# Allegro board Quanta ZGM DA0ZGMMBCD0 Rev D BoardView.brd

Outline 323.4 x 222.55 mm; copper layers: TOP, SGND, IN1, SGND1, IN2, SVCC, SVCC1, IN3, SGND2, IN4, SGND3, BOTTOM. Coordinates in mm from the lower left corner of the outline.
Outline path: 0,100.22 0,98.15 0.5,97.64 5.68,97.64 arc(6.18,98.15) 6.68,97.64 6.68,88.3 arc(6.18,87.81) 5.68,88.3 1,88.3 1,83.64 5.68,83.64 arc(6.18,84.15) 6.68,83.64 6.68,74.3 arc(6.18,73.81) 5.68,74.3 0.5,74.3 0,73.8 0,72.35 0.5,71.85 1.6,71.85 2,71.45 2,70.4 2.4,70 4,70 arc(5.25,68.75) 4,67.5 2.4,67.5 2,67.1 2,63.76 2.1,63.76 2.5,63.36 2.5,62.05 2.1,61.65 0.5,61.65 0,61.15 0,59.4 13.8,59.4 arc(14.3,58.9) 13.8,58.4 13.8,46.7 arc(14.3,46.2) 13.8,45.7 0,45.7 0,43.8 2.2,43.8 2.2,40.8 8.69,40.8 arc(9.19,41.3) 9.69,40.8 9.69,25.2 arc(9.19,24.7) 8.69,25.2 0,25.2 0,22.71 1.6,22.71 2,22.31 2,19.71 11.5,19.71 arc(11.9,19.31) 11.5,18.91 11.5,11.41 arc(11.9,11.01) 11.5,10.61 2,10.61 2,1.5 3.5,0 28.41,0 arc(29.12,0.29) 29.41,1 29.41,29 32.41,32 51.41,32 51.41,36 58.2,36 60.7,38.5 118.7,38.5 120.7,36.5 215.7,36.5 218.2,34 220.9,34 221.4,34.5 221.4,37 arc(222.7,38.3) 224,37 224,34.5 224.5,34 273.19,34 273.69,34.5 273.69,37 arc(274.99,38.3) 276.29,37 276.29,34.5 276.79,34 289.6,34 arc(290.31,34.29) 290.6,35 290.6,54.2 293.6,57.2 322.4,57.2 arc(323.11,57.49) 323.4,58.2 323.4,101.52 arc(323.19,102.13) 322.65,102.48 arc(318.22,103.89) 313.96,105.74 arc(313.62,105.78) 313.33,105.58 312.43,104.28 arc(305.61,103.03) 304.37,109.85 305.12,110.94 arc(305.2,111.29) 305.02,111.61 arc(304.61,111.95) 304.21,112.3 arc(293.01,127.38) 288.9,145.71 288.9,218.9 arc(288.61,219.61) 287.9,219.9 252.9,219.9 252.9,220.65 arc(252.61,221.36) 251.9,221.65 221.74,221.65 arc(220.15,222.55) 218.56,221.65 218.45,221.65 218.45,210.78 arc(218.8,209.93) 217.95,210.28 205.85,210.28 arc(205,209.93) 205.35,210.78 205.35,221.65 205.24,221.65 arc(203.65,222.55) 202.06,221.65 193.74,221.65 arc(192.15,222.55) 190.56,221.65 190.45,221.65 190.45,210.78 arc(190.8,209.93) 189.95,210.28 177.85,210.28 arc(177,209.93) 177.35,210.78 177.35,221.65 177.24,221.65 arc(175.65,222.55) 174.06,221.65 143.9,221.65 arc(143.19,221.36) 142.9,220.65 142.9,219.9 107.9,219.9 arc(107.19,219.61) 106.9,218.9 106.9,147.91 arc(102.73,128.68) 90.96,112.92 arc(90.62,112.62) 90.27,112.34 arc(90.1,112.02) 90.18,111.67 91.43,109.85 arc(90.19,103.03) 83.37,104.28 81.66,106.75 arc(81.38,106.95) 81.04,106.93 arc(72.31,104.15) 63.2,103.21 4.3,103.21 arc(3.59,102.92) 3.3,102.21 3.3,100.22 0,100.22

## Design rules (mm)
constraint set DEFAULT: min track width 0.14
net group DFP-S5W5-T14B: nets VGPU_CORE_SENSE VSS_GPU_SENSE
net group DFP-S7W5.5-TB: nets VGA_XTALIN VGA_XTALOUT
net group W5.5-T1234B: nets SUSCLK SUSCLK_32K
net group W25-T1234B: nets LED_PWR_LEFT LED_PWR_RIGHT
net group DFP-S3.5(4.5)W6(5)-T14B: nets M_A_CLKN0 M_A_CLKN1 M_A_CLKP0 M_A_CLKP1 M_A_DQSN0 M_A_DQSN1 M_A_DQSN2 M_A_DQSN3 M_A_DQSN4 M_A_DQSN5 M_A_DQSN6 M_A_DQSN7 M_A_DQSP0 M_A_DQSP1 M_A_DQSP2 M_A_DQSP3 M_A_DQSP4 M_A_DQSP5 M_A_DQSP6 M_A_DQSP7 M_B_CLKN0 M_B_CLKN1 M_B_CLKP0 M_B_CLKP1 M_B_DQSN0 M_B_DQSN1 M_B_DQSN2 M_B_DQSN3 M_B_DQSN4 M_B_DQSN5 M_B_DQSN6 M_B_DQSN7 M_B_DQSP0 M_B_DQSP1 M_B_DQSP2 M_B_DQSP3 M_B_DQSP4 M_B_DQSP5 M_B_DQSP6 M_B_DQSP7
net group DFP-S4(4.5)W5.5(4.5)-T14B: nets USB3_PCH_RX_WWAN_TX_C_N USB3_PCH_RX_WWAN_TX_C_P USB3_PCH_TX_WWAN_RX_C_N USB3_PCH_TX_WWAN_RX_C_P USB30_RX+_DB1 USB30_RX+_DB2 USB30_RX+_MB1 USB30_RX+_MB1_RTO USB30_RX+_WWAN USB30_RX-_DB1 USB30_RX-_DB2 USB30_RX-_MB1 USB30_RX-_MB1_RTO USB30_RX-_WWAN USB30_TX+_DB1 USB30_TX+_DB2 USB30_TX+_MB1 USB30_TX+_MB1_RTI USB30_TX+_WWAN USB30_TX-_DB1 USB30_TX-_DB2 USB30_TX-_MB1 USB30_TX-_MB1_RTI USB30_TX-_WWAN
net group DFP-S4(4.5: nets VMA_CLK0 VMA_CLK0# VMA_CLK1 VMA_CLK1# VMA_WCK01 VMA_WCK01# VMA_WCK23 VMA_WCK23# VMA_WCK45 VMA_WCK45# VMA_WCK67 VMA_WCK67# VMA_WCKB01 VMA_WCKB01# VMA_WCKB23 VMA_WCKB23# VMA_WCKB45 VMA_WCKB45# VMA_WCKB67 VMA_WCKB67# VMB_CLK0 VMB_CLK0# VMB_CLK1 VMB_CLK1# VMB_WCK01 VMB_WCK01# VMB_WCK23 VMB_WCK23# VMB_WCK45 VMB_WCK45# VMB_WCK67 VMB_WCK67# VMB_WCKB01 VMB_WCKB01# VMB_WCKB23 VMB_WCKB23# VMB_WCKB45 VMB_WCKB45# VMB_WCKB67 VMB_WCKB67# VMC_CLK0 VMC_CLK0# VMC_CLK1 VMC_CLK1# VMC_WCK01 VMC_WCK01# VMC_WCK23 VMC_WCK23# VMC_WCK45 VMC_WCK45# VMC_WCK67 VMC_WCK67# VMC_WCKB01 VMC_WCKB01# VMC_WCKB23 VMC_WCKB23# VMC_WCKB45 VMC_WCKB45# VMC_WCKB67 VMC_WCKB67# VMD_CLK0 VMD_CLK0# VMD_CLK1 VMD_CLK1# VMD_WCK01 VMD_WCK01# VMD_WCK23 VMD_WCK23# VMD_WCK45 VMD_WCK45# VMD_WCK67 VMD_WCK67# VMD_WCKB01 VMD_WCKB01# VMD_WCKB23 VMD_WCKB23# VMD_WCKB45 VMD_WCKB45# VMD_WCKB67 VMD_WCKB67#
net group DFP-S5(3.1)W5.5(3.4)-T4B: nets GPU_EDP_AUXN GPU_EDP_AUXN_R GPU_EDP_AUXP GPU_EDP_AUXP_R GPU_EDP_TXN0 GPU_EDP_TXN0_R GPU_EDP_TXN1 GPU_EDP_TXN1_R GPU_EDP_TXN2 GPU_EDP_TXN2_R GPU_EDP_TXN3 GPU_EDP_TXN3_R GPU_EDP_TXP0 GPU_EDP_TXP0_R GPU_EDP_TXP1 GPU_EDP_TXP1_R GPU_EDP_TXP2 GPU_EDP_TXP2_R GPU_EDP_TXP3 GPU_EDP_TXP3_R INT_EDP_AUXN INT_EDP_AUXN_R INT_EDP_AUXP INT_EDP_AUXP_R INT_EDP_TXN0 INT_EDP_TXN0_R INT_EDP_TXN1 INT_EDP_TXN1_R INT_EDP_TXN2 INT_EDP_TXN2_R INT_EDP_TXN3 INT_EDP_TXN3_R INT_EDP_TXP0 INT_EDP_TXP0_R INT_EDP_TXP1 INT_EDP_TXP1_R INT_EDP_TXP2 INT_EDP_TXP2_R INT_EDP_TXP3 INT_EDP_TXP3_R
net group DFP-S5(3.1)W5.5(3.4)-T14B: nets 8816ARGDN 8816AVSNS FVDDQ_SENSE_I FVDDQ_SENSE_V INA199_IN+ INA199_IN- NVVDD_SENSE_I NVVDD_SENSE_V TCP0_AUX_DN TCP0_AUX_DN_R TCP0_AUX_DP TCP0_AUX_DP_R TCP0_TX_N0 TCP0_TX_N0_C TCP0_TX_N1 TCP0_TX_N1_C TCP0_TX_P0 TCP0_TX_P0_C TCP0_TX_P1 TCP0_TX_P1_C TCP0_TXRX_N0 TCP0_TXRX_N0_C TCP0_TXRX_N1 TCP0_TXRX_N1_C TCP0_TXRX_P0 TCP0_TXRX_P0_C TCP0_TXRX_P1 TCP0_TXRX_P1_C TCP2_AUX_DN TCP2_AUX_DN_R TCP2_AUX_DP TCP2_AUX_DP_R TCP2_TX_N0 TCP2_TX_N0_C TCP2_TX_N1 TCP2_TX_N1_C TCP2_TX_P0 TCP2_TX_P0_C TCP2_TX_P1 TCP2_TX_P1_C TCP2_TXRX_N0 TCP2_TXRX_N0_C TCP2_TXRX_N1 TCP2_TXRX_N1_C TCP2_TXRX_P0 TCP2_TXRX_P0_C TCP2_TXRX_P1 TCP2_TXRX_P1_C
net group DFP-S5(3.1: nets TBT_SBU1_P1_CON_S TBT_SBU1_P2_CON_S TBT_SBU2_P1_CON_S TBT_SBU2_P2_CON_S
net group DFP-S5(3.1: nets CNV_WR_CLK_DN CNV_WR_CLK_DP CNV_WR_LANE0_DN CNV_WR_LANE0_DP CNV_WR_LANE1_DN CNV_WR_LANE1_DP CNV_WT_CLK_DN CNV_WT_CLK_DP CNV_WT_LANE0_DN CNV_WT_LANE0_DP CNV_WT_LANE1_DN CNV_WT_LANE1_DP
net group DFP-S5(3.1: nets 24780_ACN 24780_ACP 24780_SRN 24780_SRP CLK_CPU_BCLKN CLK_CPU_BCLKP CLK_DPLL_NSCCLKN CLK_DPLL_NSCCLKN_C CLK_DPLL_NSCCLKP CLK_DPLL_NSCCLKP_C CLK_PCIE_LANN CLK_PCIE_LANP CLK_PCIE_SSD1N CLK_PCIE_SSD1N_R CLK_PCIE_SSD1P CLK_PCIE_SSD1P_R CLK_PCIE_SSDN CLK_PCIE_SSDN_R CLK_PCIE_SSDP CLK_PCIE_SSDP_R CLK_PCIE_WLANN CLK_PCIE_WLANP CLK_PCIE_WWANN CLK_PCIE_WWANP CLK_VGA_N CLK_VGA_P CPU_PCI_BCLKN CPU_PCI_BCLKP GPU_ADC_INN GPU_ADC_INP GPU_THERMDA GPU_THERMDC MBCLK1_GPU MBDATA1_GPU PCIE_8_PCH_RX_WWAN_TX_C_N PCIE_8_PCH_RX_WWAN_TX_C_P PCIE_8_PCH_TX_WWAN_RX_C_N PCIE_8_PCH_TX_WWAN_RX_C_P PCIE_RXN8_WWAN PCIE_RXN_LAN PCIE_RXN_WLAN PCIE_RXP8_WWAN PCIE_RXP_LAN PCIE_RXP_WLAN PCIE_TXN8_WWAN PCIE_TXN_LAN PCIE_TXN_WLAN PCIE_TXN_WLAN_C PCIE_TXP8_WWAN PCIE_TXP_LAN PCIE_TXP_WLAN PCIE_TXP_WLAN_C PEG11_RXN0_SSD PEG11_RXN0_SSD_R PEG11_RXN1_SSD PEG11_RXN1_SSD_R PEG11_RXN2_SSD PEG11_RXN2_SSD_R PEG11_RXN3_SSD PEG11_RXN3_SSD_R PEG11_RXP0_SSD PEG11_RXP0_SSD_R PEG11_RXP1_SSD PEG11_RXP1_SSD_R PEG11_RXP2_SSD PEG11_RXP2_SSD_R PEG11_RXP3_SSD PEG11_RXP3_SSD_R PEG11_TXN0_SSD PEG11_TXN0_SSD_R PEG11_TXN1_SSD PEG11_TXN1_SSD_R PEG11_TXN2_SSD PEG11_TXN2_SSD_R PEG11_TXN3_SSD PEG11_TXN3_SSD_R PEG11_TXP0_SSD PEG11_TXP0_SSD_R PEG11_TXP1_SSD PEG11_TXP1_SSD_R PEG11_TXP2_SSD PEG11_TXP2_SSD_R PEG11_TXP3_SSD PEG11_TXP3_SSD_R PEG12_RXN0_SSD PEG12_RXN0_SSD_R PEG12_RXN1_SSD PEG12_RXN1_SSD_R PEG12_RXN2_SSD PEG12_RXN2_SSD_R PEG12_RXN3_SSD PEG12_RXN3_SSD_R PEG12_RXP0_SSD PEG12_RXP0_SSD_R PEG12_RXP1_SSD PEG12_RXP1_SSD_R PEG12_RXP2_SSD PEG12_RXP2_SSD_R PEG12_RXP3_SSD PEG12_RXP3_SSD_R PEG12_TXN0_SSD PEG12_TXN0_SSD_R PEG12_TXN1_SSD PEG12_TXN1_SSD_R PEG12_TXN2_SSD PEG12_TXN2_SSD_R PEG12_TXN3_SSD PEG12_TXN3_SSD_R PEG12_TXP0_SSD PEG12_TXP0_SSD_R PEG12_TXP1_SSD PEG12_TXP1_SSD_R PEG12_TXP2_SSD PEG12_TXP2_SSD_R PEG12_TXP3_SSD PEG12_TXP3_SSD_R SATA_RXN0_CN SATA_RXN0_HDD SATA_RXN_IN SATA_RXN_OUT SATA_RXP0_CN SATA_RXP0_HDD SATA_RXP_IN SATA_RXP_OUT SATA_TXN0_CN SATA_TXN0_HDD SATA_TXN_IN SATA_TXN_OUT SATA_TXP0_CN SATA_TXP0_HDD SATA_TXP_IN SATA_TXP_OUT TBT_LSX0_RXD TBT_LSX0_RXD_C TBT_LSX0_TXD TBT_LSX0_TXD_C TBT_LSX2_RXD TBT_LSX2_RXD_C TBT_LSX2_TXD TBT_LSX2_TXD_C USBP+_CCD USBP+_CCD_R USBP+_DB1 USBP+_DB1_C USBP+_DB2 USBP+_DB2_C USBP+_KB USBP+_MB USBP+_MB_C USBP+_MB_C_R USBP+_TC1 USBP+_TC2 USBP+_WLAN USBP+_WWAN USBP+_WWAN_R USBP-_CCD USBP-_CCD_R USBP-_DB1 USBP-_DB1_C USBP-_DB2 USBP-_DB2_C USBP-_KB USBP-_MB USBP-_MB_C USBP-_MB_C_R USBP-_TC1 USBP-_TC2 USBP-_WLAN USBP-_WWAN USBP-_WWAN_R VCC_AUX_SENSE VCC_AUX_SENSE_SRC VCC_PCH_AUX_SENSE VCCSENSE VSS_AUX_SENSE VSS_AUX_SENSE_SRC VSS_PCH_AUX_SENSE VSSSENSE WWAN_CLK_C_N WWAN_CLK_C_P
net group DFP-S5(4)W5.5(4)-T14B: nets DMI_RCOMP_N DMI_RCOMP_P PCIE4_RCOMP_N PCIE4_RCOMP_P PCIE16_RCOMP_N PCIE16_RCOMP_P PCIECOMP_N PCIECOMP_P TCRCOMP_DN TCRCOMP_DP
net group DFP-S5(4: nets DMI_RXN0 DMI_RXN1 DMI_RXN2 DMI_RXN3 DMI_RXN4 DMI_RXN5 DMI_RXN6 DMI_RXN7 DMI_RXP0 DMI_RXP1 DMI_RXP2 DMI_RXP3 DMI_RXP4 DMI_RXP5 DMI_RXP6 DMI_RXP7 DMI_TXN0 DMI_TXN1 DMI_TXN2 DMI_TXN3 DMI_TXN4 DMI_TXN5 DMI_TXN6 DMI_TXN7 DMI_TXP0 DMI_TXP1 DMI_TXP2 DMI_TXP3 DMI_TXP4 DMI_TXP5 DMI_TXP6 DMI_TXP7
net group DFP-S5W5.5-TB: nets PEG_RXN0 PEG_RXN0_C PEG_RXN1 PEG_RXN1_C PEG_RXN2 PEG_RXN2_C PEG_RXN3 PEG_RXN3_C PEG_RXN4 PEG_RXN4_C PEG_RXN5 PEG_RXN5_C PEG_RXN6 PEG_RXN6_C PEG_RXN7 PEG_RXN7_C PEG_RXP0 PEG_RXP0_C PEG_RXP1 PEG_RXP1_C PEG_RXP2 PEG_RXP2_C PEG_RXP3 PEG_RXP3_C PEG_RXP4 PEG_RXP4_C PEG_RXP5 PEG_RXP5_C PEG_RXP6 PEG_RXP6_C PEG_RXP7 PEG_RXP7_C PEG_TXN0 PEG_TXN0_C PEG_TXN1 PEG_TXN1_C PEG_TXN2 PEG_TXN2_C PEG_TXN3 PEG_TXN3_C PEG_TXN4 PEG_TXN4_C PEG_TXN5 PEG_TXN5_C PEG_TXN6 PEG_TXN6_C PEG_TXN7 PEG_TXN7_C PEG_TXP0 PEG_TXP0_C PEG_TXP1 PEG_TXP1_C PEG_TXP2 PEG_TXP2_C PEG_TXP3 PEG_TXP3_C PEG_TXP4 PEG_TXP4_C PEG_TXP5 PEG_TXP5_C PEG_TXP6 PEG_TXP6_C PEG_TXP7 PEG_TXP7_C TBT_SBU1_P1_CON TBT_SBU1_P2_CON TBT_SBU2_P1_CON TBT_SBU2_P2_CON TBTA_RX1_N TBTA_RX1_P TBTA_RX2_N TBTA_RX2_P TBTA_SSRX1_N TBTA_SSRX1_N_C TBTA_SSRX1_P TBTA_SSRX1_P_C TBTA_SSRX2_N TBTA_SSRX2_N_C TBTA_SSRX2_P TBTA_SSRX2_P_C TBTA_SSTX1_N TBTA_SSTX1_N_C TBTA_SSTX1_P TBTA_SSTX1_P_C TBTA_SSTX2_N TBTA_SSTX2_N_C TBTA_SSTX2_P TBTA_SSTX2_P_C TBTA_TX1_N TBTA_TX1_P TBTA_TX2_N TBTA_TX2_P TBTB_RX1_N TBTB_RX1_P TBTB_RX2_N TBTB_RX2_P TBTB_SSRX1_N TBTB_SSRX1_N_C TBTB_SSRX1_P TBTB_SSRX1_P_C TBTB_SSRX2_N TBTB_SSRX2_N_C TBTB_SSRX2_P TBTB_SSRX2_P_C TBTB_SSTX1_N TBTB_SSTX1_N_C TBTB_SSTX1_P TBTB_SSTX1_P_C TBTB_SSTX2_N TBTB_SSTX2_N_C TBTB_SSTX2_P TBTB_SSTX2_P_C TBTB_TX1_N TBTB_TX1_P TBTB_TX2_N TBTB_TX2_P
net group DFP-S6W30-T1234B: nets L_SPK+ L_SPK+_C L_SPK- L_SPK-_C R_SPK+ R_SPK+_C R_SPK- R_SPK-_C
net group DFP-S7(4)W5.5(3.4)-T1B: nets C_OUT_DP_TXN0 C_OUT_DP_TXN1 C_OUT_DP_TXN2 C_OUT_DP_TXN3 C_OUT_DP_TXP0 C_OUT_DP_TXP1 C_OUT_DP_TXP2 C_OUT_DP_TXP3 DP_D0 DP_D0# DP_D1 DP_D1# DP_D2 DP_D2# DP_D3 DP_D3# DP_TXN0_R DP_TXN1_R DP_TXN2_R DP_TXN3_R DP_TXP0_R DP_TXP1_R DP_TXP2_R DP_TXP3_R OUT_DP_TXN0 OUT_DP_TXN1 OUT_DP_TXN2 OUT_DP_TXN3 OUT_DP_TXP0 OUT_DP_TXP1 OUT_DP_TXP2 OUT_DP_TXP3
net group DFP-S7(4)W5.5(3.4)-T14B: nets INT_DP0_AUXN INT_DP0_AUXN_C INT_DP0_AUXP INT_DP0_AUXP_C INT_DP0_D0 INT_DP0_D0# INT_DP0_D0#_C INT_DP0_D0_C INT_DP0_D1 INT_DP0_D1# INT_DP0_D1#_C INT_DP0_D1_C INT_DP0_D2 INT_DP0_D2# INT_DP0_D2#_C INT_DP0_D2_C INT_DP0_D3 INT_DP0_D3# INT_DP0_D3#_C INT_DP0_D3_C INT_DP1_AUXN INT_DP1_AUXN_C INT_DP1_AUXP INT_DP1_AUXP_C INT_DP1_D0 INT_DP1_D0# INT_DP1_D0#_C INT_DP1_D0_C INT_DP1_D1 INT_DP1_D1# INT_DP1_D1#_C INT_DP1_D1_C INT_DP1_D2 INT_DP1_D2# INT_DP1_D2#_C INT_DP1_D2_C INT_DP1_D3 INT_DP1_D3# INT_DP1_D3#_C INT_DP1_D3_C INT_DP2_AUXN INT_DP2_AUXN_C INT_DP2_AUXP INT_DP2_AUXP_C INT_DP2_D0 INT_DP2_D0# INT_DP2_D0#_C INT_DP2_D0_C INT_DP2_D1 INT_DP2_D1# INT_DP2_D1#_C INT_DP2_D1_C INT_DP2_D2 INT_DP2_D2# INT_DP2_D2#_C INT_DP2_D2_C INT_DP2_D3 INT_DP2_D3# INT_DP2_D3#_C INT_DP2_D3_C
net group DFP-S7(4: nets C_INT_DP_AUXN C_INT_DP_AUXP INT_DP_AUXN INT_DP_AUXN_Q INT_DP_AUXP INT_DP_AUXP_Q
net group DFP-S11(6)W5.5(3.4)-T1B: nets C_TX0_HDMI+ C_TX0_HDMI- C_TX1_HDMI+ C_TX1_HDMI- C_TX2_HDMI+ C_TX2_HDMI- C_TXC_HDMI+ C_TXC_HDMI- GPU_CLK GPU_CLK# GPU_CLK#_C GPU_CLK_C GPU_D0 GPU_D0# GPU_D0#_C GPU_D0_C GPU_D1 GPU_D1# GPU_D1#_C GPU_D1_C GPU_D2 GPU_D2# GPU_D2#_C GPU_D2_C TX0_HDMI+ TX0_HDMI- TX1_HDMI+ TX1_HDMI- TX2_HDMI+ TX2_HDMI- TXC_HDMI+ TXC_HDMI-
net group DFP-S11(6)W5.5(3.4)-T14B: nets USB30_RX+_MB1_C USB30_RX+_MB1_C_R USB30_RX+_MB1_RTI USB30_RX-_MB1_C USB30_RX-_MB1_C_R USB30_RX-_MB1_RTI USB30_TX+_MB1_C USB30_TX+_MB1_C_R USB30_TX+_MB1_RTO USB30_TX-_MB1_C USB30_TX-_MB1_C_R USB30_TX-_MB1_RTO
net group DFP-S11(7.5: nets C_OUT_EDP_TXN0 C_OUT_EDP_TXN1 C_OUT_EDP_TXN2 C_OUT_EDP_TXN3 C_OUT_EDP_TXP0 C_OUT_EDP_TXP1 C_OUT_EDP_TXP2 C_OUT_EDP_TXP3 EDP_AUX#_C EDP_AUX#_C_R EDP_AUX_C EDP_AUX_C_R EDP_TXN0_C EDP_TXN1_C EDP_TXN2_C EDP_TXN3_C EDP_TXP0_C EDP_TXP1_C EDP_TXP2_C EDP_TXP3_C
net group W5-T14B: nets FBVDDQ_SENSE
net group W5-T1234B: nets FB_CAL_PD_VDDQ FB_CAL_PU_GND FB_CAL_TERM_GND
net group W5.5(3.4: nets CNV_BRI_DT CNV_BRI_DT_C CNV_BRI_RSP CNV_BRI_RSP_R CNV_RGI_DT CNV_RGI_DT_C CNV_RGI_RSP CNV_RGI_RSP_R
net group W5.5(3.4: nets 2ND_MBCLK 2ND_MBCLK_DDR 2ND_MBDATA 2ND_MBDATA_DDR 3ND_MBCLK 3ND_MBCLK_C 3ND_MBCLK_GPU 3ND_MBDATA 3ND_MBDATA_C 3ND_MBDATA_GPU 1006_I2C_SCL 1006_I2C_SDA 1006_I2S_BCLK 1006_I2S_BCLK_R 1006_I2S_IN 1006_I2S_IN_R 1006_I2S_LRCK 1006_I2S_LRCK_R 1006_I2S_MCLK 1006_I2S_MCLK_R 1006_I2S_OUT 1006_I2S_OUT_R 2211_HPD# 2211_SCL 2211_SDA 81305_ALERT# 81305_CSCOMP 81305_SCLK 81305_SDIO ACZ_BCLK ACZ_RST# ACZ_RST#_AUDIO ACZ_SDIN0 ACZ_SDIN0_U ACZ_SDOUT ACZ_SDOUT_AUDIO ACZ_SPKR ACZ_SYNC ACZ_SYNC_AUDIO AMP_MUTE# AUD_AZACPU_SCLK AUD_AZACPU_SCLK_R AUD_AZACPU_SDI AUD_AZACPU_SDI_R AUD_AZACPU_SDO AUD_AZACPU_SDO_R BEEP1 BEEP2 BEEP3 BIT_CLK_AUDIO BIT_CLK_AUDIO_U BL_ON CAP+ CAP- CNV_RF_RESET# CNV_RF_RESET_L CPU_EDP_HPD CPU_EDP_HPD_R CPU_PLTRST# CPU_PLTRST#R DC-DET DDR4_SUSON_2V5 DGPU_HOLD_RST# DGPU_OPP# DGPU_OPP#_PROCHOT# DMIC_CLK DMIC_CLK0 DMIC_CLK_C DMIC_CLK_U DMIC_DAT DMIC_DAT0 DMIC_DAT_U DMIC_DATA_C DP_HPD DP_HPD_PCH DP_HPD_PCH_Q EAPD EC_I2C_SCL_D EC_I2C_SDA_D EC_PECI EC_PECI_R EC_PWROK EC_PWROK_R EDP_I2C_CLK EDP_I2C_CLK_C EDP_I2C_DATA EDP_I2C_DATA_C ESPI_CLK FAN1_PWM FAN1_PWM_Q FAN1_RPM FAN2_PWM FAN2_PWM_Q FAN2_RPM FRM_LCK# GFX_SCL GFX_SDA GPU_DDCCLK GPU_DDCDATA GPU_THROTTING# GPUT_CLK GPUT_DATA H_CPU_SVIDALRT# H_CPU_SVIDDAT H_PROCHOT# H_VCCST_PWRGD HDMI_HPD_GPU HDMI_HPD_PCH HDMI_SCLK HDMI_SDATA HP_JD# HP_JD_C# HWPG HWPG_1.8VS5 HWPG_2.5V HWPG_VDDR I2C_TP_SCL_C I2C_TP_SDA_C I2CB_SCL_G I2CB_SDA_G I2CC_SCL_GFX I2CC_SDA_GFX IMVP_PWRGD LCD_BL_PWM LCD_BLEN LCD_VDD LID# LID#_EC_L LINEOUT_LED LINEOUT_LED_C MAINON MB_THRMTRIP# MBCLK MBCLK_CONN MBDATA MBDATA_CONN MIC-JD MODEM_CLKREQ MODEM_CLKREQ_L N45113988 N48158687 N80576314 N82987111 N82987114 N88395011 NGFF1_RST# NGFF2_RST# PCBEEP_EC PCH_AZ_CODEC_RST#_PD PCH_DMIC_CLK PCH_DMIC_DAT PCH_PWROK PCH_SPI1_CLK PCH_SPI1_CLK_R PCH_SPI1_SI PCH_SPI1_SI_R PCH_SPI1_SO PCH_SPI1_SO_R PCH_SPI_CLK_EC PCH_SPI_CS0# PCH_SPI_CS0#_R PCH_SPI_IO2 PCH_SPI_IO2_R PCH_SPI_IO3 PCH_SPI_IO3_R PCH_SPI_SI_EC PCH_SPI_SO_EC PCIE_CLKREQ6# PCIE_CLKREQ7# PCIE_CLKREQ_LAN# PCIE_CLKREQ_SSD1# PCIE_CLKREQ_SSD# PCIE_CLKREQ_VGA# PCIE_CLKREQ_WLAN# PCIE_CLKREQ_WWAN# PD# PD_I2C_SCL PD_I2C_SDA PEGX_RST# PEX_CLKREQ PLTRST# PLTRST#_EC PM_THRMTRIP# PM_THRMTRIP#_P PROCHOT_EC PS1_I2C_SCL PS1_I2C_SDA PS1_MBCLK PS1_MBDATA PS2_I2C_SCL PS2_I2C_SDA PS2_MBCLK PS2_MBDATA PS8811_MBCLK PS8811_MBDATA PS8817_MBCLK PS8817_MBDATA RSMRST# RT_I2C_SCL RT_I2C_SCL_D RT_I2C_SDA RT_I2C_SDA_D RTC_RST# S5_ON SLP_A# SMB_PCH_CLK SMB_PCH_DAT SMB_RUN_CLK SMB_RUN_DAT SMB_SML0_CLK SMB_SML0_DAT SPI1_CLK_R SPI1_SI_R SPI1_SO_R SPI_CS0#_R SPI_CS0#_UR_ME SPI_IO2_R SPI_IO3_R SPK_LED_ON_OFF SRTC_RST# SUSB# SUSC# SUSON SYS_HWPG SYS_PWROK TCP0_FLASH_CLK TCP0_FLASH_CS# TCP0_FLASH_DI TCP0_FLASH_DO TCP0_FLASH_HOLD# TCP0_FLASH_WP# TCP1_FLASH_CLK TCP1_FLASH_CS# TCP1_FLASH_DI TCP1_FLASH_DO TCP_RETIMER_PERST# TP_CLK TP_DAT TP_I2C_SCL TP_I2C_SDA TPM_SPI1_CLK TPM_SPI1_SI TPM_SPI1_SO ULT_EDP_HPD ULT_EDP_HPD_R VCCAUX_VID0 VCCAUX_VID1 VR_SVID_ALERT# VR_SVID_CLK VR_SVID_CLK_R VR_SVID_DATA VRON WLAN_CLKREQ# WLAN_RST# WWAN_SIM1_CLK WWAN_SIM1_CLK_C WWAN_SIM1_DATA WWAN_SIM1_DATA_C
net group W5.5-TB: nets RTC_X1 RTC_X1_C RTC_X2 RTC_X2_C VGA_XTALOUT_R XTAL38P4_IN XTAL38P4_IN_L XTAL38P4_OUT XTAL38P4_OUT_L XTAL_TCP0_25MHZ_IN XTAL_TCP0_25MHZ_OUT XTAL_TCP1_25MHZ_IN XTAL_TCP1_25MHZ_OUT XTALOUT_RC XTALOUTBUFF XTALSSIN
net group W6.5(4: nets FBA_CMD0 FBA_CMD1 FBA_CMD2 FBA_CMD3 FBA_CMD4 FBA_CMD5 FBA_CMD6 FBA_CMD7 FBA_CMD8 FBA_CMD9 FBA_CMD10 FBA_CMD11 FBA_CMD12 FBA_CMD13 FBA_CMD14 FBA_CMD15 FBA_CMD16 FBA_CMD17 FBA_CMD18 FBA_CMD19 FBA_CMD20 FBA_CMD21 FBA_CMD22 FBA_CMD23 FBA_CMD24 FBA_CMD28 FBA_CMD29 FBA_CMD30 FBA_CMD31 FBA_CMD32 FBA_CMD33 FBA_CMD34 FBA_CMD35 FBA_CMD36 FBA_CMD37 FBA_CMD38 FBA_CMD39 FBA_CMD40 FBA_CMD41 FBA_CMD42 FBA_CMD43 FBA_CMD44 FBA_CMD45 FBA_CMD46 FBA_CMD47 FBA_CMD48 FBA_CMD49 FBA_CMD50 FBA_CMD51 FBA_CMD52 FBB_CMD0 FBB_CMD1 FBB_CMD2 FBB_CMD3 FBB_CMD4 FBB_CMD5 FBB_CMD6 FBB_CMD7 FBB_CMD8 FBB_CMD9 FBB_CMD10 FBB_CMD11 FBB_CMD12 FBB_CMD13 FBB_CMD14 FBB_CMD15 FBB_CMD16 FBB_CMD17 FBB_CMD18 FBB_CMD19 FBB_CMD20 FBB_CMD21 FBB_CMD22 FBB_CMD23 FBB_CMD24 FBB_CMD28 FBB_CMD29 FBB_CMD30 FBB_CMD31 FBB_CMD32 FBB_CMD33 FBB_CMD34 FBB_CMD35 FBB_CMD36 FBB_CMD37 FBB_CMD38 FBB_CMD39 FBB_CMD40 FBB_CMD41 FBB_CMD42 FBB_CMD43 FBB_CMD44 FBB_CMD45 FBB_CMD46 FBB_CMD47 FBB_CMD48 FBB_CMD49 FBB_CMD50 FBB_CMD51 FBB_CMD52 FBC_CMD0 FBC_CMD1 FBC_CMD2 FBC_CMD3 FBC_CMD4 FBC_CMD5 FBC_CMD6 FBC_CMD7 FBC_CMD8 FBC_CMD9 FBC_CMD10 FBC_CMD11 FBC_CMD12 FBC_CMD13 FBC_CMD14 FBC_CMD15 FBC_CMD16 FBC_CMD17 FBC_CMD18 FBC_CMD19 FBC_CMD20 FBC_CMD21 FBC_CMD22 FBC_CMD23 FBC_CMD24 FBC_CMD28 FBC_CMD29 FBC_CMD30 FBC_CMD31 FBC_CMD32 FBC_CMD33 FBC_CMD34 FBC_CMD35 FBC_CMD36 FBC_CMD37 FBC_CMD38 FBC_CMD39 FBC_CMD40 FBC_CMD41 FBC_CMD42 FBC_CMD43 FBC_CMD44 FBC_CMD45 FBC_CMD46 FBC_CMD47 FBC_CMD48 FBC_CMD49 FBC_CMD50 FBC_CMD51 FBC_CMD52 FBD_CMD0 FBD_CMD1 FBD_CMD2 FBD_CMD3 FBD_CMD4 FBD_CMD5 FBD_CMD6 FBD_CMD7 FBD_CMD8 FBD_CMD9 FBD_CMD10 FBD_CMD11 FBD_CMD12 FBD_CMD13 FBD_CMD14 FBD_CMD15 FBD_CMD16 FBD_CMD17 FBD_CMD18 FBD_CMD19 FBD_CMD20 FBD_CMD21 FBD_CMD22 FBD_CMD23 FBD_CMD24 FBD_CMD28 FBD_CMD29 FBD_CMD30 FBD_CMD31 FBD_CMD32 FBD_CMD33 FBD_CMD34 FBD_CMD35 FBD_CMD36 FBD_CMD37 FBD_CMD38 FBD_CMD39 FBD_CMD40 FBD_CMD41 FBD_CMD42 FBD_CMD43 FBD_CMD44 FBD_CMD45 FBD_CMD46 FBD_CMD47 FBD_CMD48 FBD_CMD49 FBD_CMD50 FBD_CMD51 FBD_CMD52
net group W7.5(4.5: nets DDR4_DRAMRST#
net group W8-T1234B: nets IFPAB_RSET IFPC_RSET IFPEF_RSET VCORE_CSN1 VCORE_CSN2 VCORE_CSN3 VCORE_CSN4 VCORE_CSN5 VCORE_CSN6 VCORE_CSP1 VCORE_CSP2 VCORE_CSP3 VCORE_CSP4 VCORE_CSP5 VCORE_CSP6
net group W8.5(5: nets FBA_DBI0 FBA_DBI1 FBA_DBI2 FBA_DBI3 FBA_DBI4 FBA_DBI5 FBA_DBI6 FBA_DBI7 FBA_EDC0 FBA_EDC1 FBA_EDC2 FBA_EDC3 FBA_EDC4 FBA_EDC5 FBA_EDC6 FBA_EDC7 FBB_DBI0 FBB_DBI1 FBB_DBI2 FBB_DBI3 FBB_DBI4 FBB_DBI5 FBB_DBI6 FBB_DBI7 FBB_EDC0 FBB_EDC1 FBB_EDC2 FBB_EDC3 FBB_EDC4 FBB_EDC5 FBB_EDC6 FBB_EDC7 FBC_DBI0 FBC_DBI1 FBC_DBI2 FBC_DBI3 FBC_DBI4 FBC_DBI5 FBC_DBI6 FBC_DBI7 FBC_EDC0 FBC_EDC1 FBC_EDC2 FBC_EDC3 FBC_EDC4 FBC_EDC5 FBC_EDC6 FBC_EDC7 FBD_DBI0 FBD_DBI1 FBD_DBI2 FBD_DBI3 FBD_DBI4 FBD_DBI5 FBD_DBI6 FBD_DBI7 FBD_EDC0 FBD_EDC1 FBD_EDC2 FBD_EDC3 FBD_EDC4 FBD_EDC5 FBD_EDC6 FBD_EDC7 VMA_DQ0 VMA_DQ1 VMA_DQ2 VMA_DQ3 VMA_DQ4 VMA_DQ5 VMA_DQ6 VMA_DQ7 VMA_DQ8 VMA_DQ9 VMA_DQ10 VMA_DQ11 VMA_DQ12 VMA_DQ13 VMA_DQ14 VMA_DQ15 VMA_DQ16 VMA_DQ17 VMA_DQ18 VMA_DQ19 VMA_DQ20 VMA_DQ21 VMA_DQ22 VMA_DQ23 VMA_DQ24 VMA_DQ25 VMA_DQ26 VMA_DQ27 VMA_DQ28 VMA_DQ29 VMA_DQ30 VMA_DQ31 VMA_DQ32 VMA_DQ33 VMA_DQ34 VMA_DQ35 VMA_DQ36 VMA_DQ37 VMA_DQ38 VMA_DQ39 VMA_DQ40 VMA_DQ41 VMA_DQ42 VMA_DQ43 VMA_DQ44 VMA_DQ45 VMA_DQ46 VMA_DQ47 VMA_DQ48 VMA_DQ49 VMA_DQ50 VMA_DQ51 VMA_DQ52 VMA_DQ53 VMA_DQ54 VMA_DQ55 VMA_DQ56 VMA_DQ57 VMA_DQ58 VMA_DQ59 VMA_DQ60 VMA_DQ61 VMA_DQ62 VMA_DQ63 VMB_DQ0 VMB_DQ1 VMB_DQ2 VMB_DQ3 VMB_DQ4 VMB_DQ5 VMB_DQ6 VMB_DQ7 VMB_DQ8 VMB_DQ9 VMB_DQ10 VMB_DQ11 VMB_DQ12 VMB_DQ13 VMB_DQ14 VMB_DQ15 VMB_DQ16 VMB_DQ17 VMB_DQ18 VMB_DQ19 VMB_DQ20 VMB_DQ21 VMB_DQ22 VMB_DQ23 VMB_DQ24 VMB_DQ25 VMB_DQ26 VMB_DQ27 VMB_DQ28 VMB_DQ29 VMB_DQ30 VMB_DQ31 VMB_DQ32 VMB_DQ33 VMB_DQ34 VMB_DQ35 VMB_DQ36 VMB_DQ37 VMB_DQ38 VMB_DQ39 VMB_DQ40 VMB_DQ41 VMB_DQ42 VMB_DQ43 VMB_DQ44 VMB_DQ45 VMB_DQ46 VMB_DQ47 VMB_DQ48 VMB_DQ49 VMB_DQ50 VMB_DQ51 VMB_DQ52 VMB_DQ53 VMB_DQ54 VMB_DQ55 VMB_DQ56 VMB_DQ57 VMB_DQ58 VMB_DQ59 VMB_DQ60 VMB_DQ61 VMB_DQ62 VMB_DQ63 VMC_DQ0 VMC_DQ1 VMC_DQ2 VMC_DQ3 VMC_DQ4 VMC_DQ5 VMC_DQ6 VMC_DQ7 VMC_DQ8 VMC_DQ9 VMC_DQ10 VMC_DQ11 VMC_DQ12 VMC_DQ13 VMC_DQ14 VMC_DQ15 VMC_DQ16 VMC_DQ17 VMC_DQ18 VMC_DQ19 VMC_DQ20 VMC_DQ21 VMC_DQ22 VMC_DQ23 VMC_DQ24 VMC_DQ25 VMC_DQ26 VMC_DQ27 VMC_DQ28 VMC_DQ29 VMC_DQ30 VMC_DQ31 VMC_DQ32 VMC_DQ33 VMC_DQ34 VMC_DQ35 VMC_DQ36 VMC_DQ37 VMC_DQ38 VMC_DQ39 VMC_DQ40 VMC_DQ41 VMC_DQ42 VMC_DQ43 VMC_DQ44 VMC_DQ45 VMC_DQ46 VMC_DQ47 VMC_DQ48 VMC_DQ49 VMC_DQ50 VMC_DQ51 VMC_DQ52 VMC_DQ53 VMC_DQ54 VMC_DQ55 VMC_DQ56 VMC_DQ57 VMC_DQ58 VMC_DQ59 VMC_DQ60 VMC_DQ61 VMC_DQ62 VMC_DQ63 VMD_DQ0 VMD_DQ1 VMD_DQ2 VMD_DQ3 VMD_DQ4 VMD_DQ5 VMD_DQ6 VMD_DQ7 VMD_DQ8 VMD_DQ9 VMD_DQ10 VMD_DQ11 VMD_DQ12 VMD_DQ13 VMD_DQ14 VMD_DQ15 VMD_DQ16 VMD_DQ17 VMD_DQ18 VMD_DQ19 VMD_DQ20 VMD_DQ21 VMD_DQ22 VMD_DQ23 VMD_DQ24 VMD_DQ25 VMD_DQ26 VMD_DQ27 VMD_DQ28 VMD_DQ29 VMD_DQ30 VMD_DQ31 VMD_DQ32 VMD_DQ33 VMD_DQ34 VMD_DQ35 VMD_DQ36 VMD_DQ37 VMD_DQ38 VMD_DQ39 VMD_DQ40 VMD_DQ41 VMD_DQ42 VMD_DQ43 VMD_DQ44 VMD_DQ45 VMD_DQ46 VMD_DQ47 VMD_DQ48 VMD_DQ49 VMD_DQ50 VMD_DQ51 VMD_DQ52 VMD_DQ53 VMD_DQ54 VMD_DQ55 VMD_DQ56 VMD_DQ57 VMD_DQ58 VMD_DQ59 VMD_DQ60 VMD_DQ61 VMD_DQ62 VMD_DQ63
net group W8.5(5: nets M_A_A0 M_A_A1 M_A_A2 M_A_A3 M_A_A4 M_A_A5 M_A_A6 M_A_A7 M_A_A8 M_A_A9 M_A_A10 M_A_A11 M_A_A12 M_A_A13 M_A_ACT# M_A_BA0 M_A_BA1 M_A_BG#0 M_A_BG#1 M_A_CAS# M_A_CKE0 M_A_CKE1 M_A_CS#0 M_A_CS#1 M_A_DIM0_ODT0 M_A_DIM0_ODT1 M_A_DQ0 M_A_DQ1 M_A_DQ2 M_A_DQ3 M_A_DQ4 M_A_DQ5 M_A_DQ6 M_A_DQ7 M_A_DQ8 M_A_DQ9 M_A_DQ10 M_A_DQ11 M_A_DQ12 M_A_DQ13 M_A_DQ14 M_A_DQ15 M_A_DQ16 M_A_DQ17 M_A_DQ18 M_A_DQ19 M_A_DQ20 M_A_DQ21 M_A_DQ22 M_A_DQ23 M_A_DQ24 M_A_DQ25 M_A_DQ26 M_A_DQ27 M_A_DQ28 M_A_DQ29 M_A_DQ30 M_A_DQ31 M_A_DQ32 M_A_DQ33 M_A_DQ34 M_A_DQ35 M_A_DQ36 M_A_DQ37 M_A_DQ38 M_A_DQ39 M_A_DQ40 M_A_DQ41 M_A_DQ42 M_A_DQ43 M_A_DQ44 M_A_DQ45 M_A_DQ46 M_A_DQ47 M_A_DQ48 M_A_DQ49 M_A_DQ50 M_A_DQ51 M_A_DQ52 M_A_DQ53 M_A_DQ54 M_A_DQ55 M_A_DQ56 M_A_DQ57 M_A_DQ58 M_A_DQ59 M_A_DQ60 M_A_DQ61 M_A_DQ62 M_A_DQ63 M_A_PARITY M_A_RAS# M_A_WE# M_B_A0 M_B_A1 M_B_A2 M_B_A3 M_B_A4 M_B_A5 M_B_A6 M_B_A7 M_B_A8 M_B_A9 M_B_A10 M_B_A11 M_B_A12 M_B_A13 M_B_ACT# M_B_BA0 M_B_BA1 M_B_BG#0 M_B_BG#1 M_B_CAS# M_B_CKE0 M_B_CKE1 M_B_CS#0 M_B_CS#1 M_B_DIM0_ODT0 M_B_DIM0_ODT1 M_B_DQ0 M_B_DQ1 M_B_DQ2 M_B_DQ3 M_B_DQ4 M_B_DQ5 M_B_DQ6 M_B_DQ7 M_B_DQ8 M_B_DQ9 M_B_DQ10 M_B_DQ11 M_B_DQ12 M_B_DQ13 M_B_DQ14 M_B_DQ15 M_B_DQ16 M_B_DQ17 M_B_DQ18 M_B_DQ19 M_B_DQ20 M_B_DQ21 M_B_DQ22 M_B_DQ23 M_B_DQ24 M_B_DQ25 M_B_DQ26 M_B_DQ27 M_B_DQ28 M_B_DQ29 M_B_DQ30 M_B_DQ31 M_B_DQ32 M_B_DQ33 M_B_DQ34 M_B_DQ35 M_B_DQ36 M_B_DQ37 M_B_DQ38 M_B_DQ39 M_B_DQ40 M_B_DQ41 M_B_DQ42 M_B_DQ43 M_B_DQ44 M_B_DQ45 M_B_DQ46 M_B_DQ47 M_B_DQ48 M_B_DQ49 M_B_DQ50 M_B_DQ51 M_B_DQ52 M_B_DQ53 M_B_DQ54 M_B_DQ55 M_B_DQ56 M_B_DQ57 M_B_DQ58 M_B_DQ59 M_B_DQ60 M_B_DQ61 M_B_DQ62 M_B_DQ63 M_B_PARITY M_B_RAS# M_B_WE#
net group W10-T14B: nets CFG_RCOMP CNV_WT_RCOMP CSI_RCOMP DPIP0_RCOMP DPIP1_RCOMP DPIP2_RCOMP DPIP3_RCOMP EDP_RCOMP RCOMP_1P8 SM_RCOMP_2 SNDW_RCOMP TCP_RCOMP USB2_COMP XCLK_RBIAS
net group W10-T1234B: nets +3V_EC B_CTL B_CTL_MCU B_CTL_TURBO B_CTL_TURBO_C G_CTL G_CTL_MCU G_CTL_TURBO G_CTL_TURBO_C LED_PWR_CTL1 LED_PWR_CTL2 LED_PWR_CTL3 LED_PWR_CTL4 LED_PWR_CTL5 LED_PWR_CTL6 LED_PWR_CTL7 LED_PWR_CTL_L LED_PWR_CTL_R N81221610 N81221622 N81221918 N81221920 N81221922 N81223387 N81223389 N81223391 N81223393 N81223395 N81223397 N81224848 N81224850 N81224852 N81224854 N81224856 N81224858 N84112149 N84112155 N84112164 N84113271 R_CTL R_CTL_MCU R_CTL_TURBO R_CTL_TURBO_C VCC3V3_FLASH
net group W12-T1234B: nets +1.8V_CLKLDO +3V3PD +3VPCU_EC +3VPCU_ECPLL +A3VPCU +BAT_RTC +VCCDPHY_1P24 ECAGND
net group W15-T1234B: nets +0.85V_VCCLDOSTD +3V_DEEP_SUS +3V_LDO_EC +3V_U3 +VCCPRIM_1P05_OUT +VDD_DCI HP-L2 HP-R2 MIC2-VREFO-L MIC2-VREFO-R PD_LDO_1V5 PD_LDO_3V3 TPM_VDD VCC3V3_FLASH_PD VSTBY_FSPI
net group W16-TB: nets FB_VREF_PROBE
net group W20-T134B: nets DDR1_VREF_CA0
net group W20-T1234B: nets +1.2V_U3 +1.2VSUS +1.8V +1.8V_5G +1.8V_AON +1.8V_DEEP_SUS +1.8V_S5 +1.8V_VCC +1V8_AON_U +1V_GFX +3V +3V_5G +3V_DP +3V_DVDD +3V_DVDD_IO +3V_EDPMUX +3V_HDD_REDRIVER +3V_HDMI +3V_RTC +3V_S5 +3V_SSD1 +3V_SSD2 +3V_SUS +3V_TCSS +3VPCU +3VSPI +5V_HDD +5V_HDMIC +5V_KB +5V_LED +5V_LIGHT +5V_MCU +5V_S5 +5V_S5_TYPEC +5V_TP_LED +5VA +5VPCU +12V_FAN +12V_FAN1 +12V_FAN2 +CORE_PLLVDD +FBA_PLL_AVDD +FBVDDQ_MEM +PCH_AUX +PEX_PLL_HVDD +TPVDD +USBPWR3 +USBPWR_DB1 +USBPWR_DB2 +V3.3DX_RT_TCP0 +V3.3DX_RT_TCP1 +VCC0V9_SVR_TCP0 +VCC0V9_SVR_TCP1 +VCC1.05_OUT_FET +VCC3P3_ANA_TCP0 +VCC3P3_ANA_TCP1 +VCC3P3_LC_TCP0 +VCC3P3_LC_TCP1 +VCC3V3_SX_TCP0 +VCC3V3_SX_TCP1 +VCC_CORE +VCCIN_AUX +VCCIO_OUT +VCCST +VCCSTG +VCCSTG_OUT_1 +VCCSTG_OUT_23456 +VIN_PANEL_R +WL_VDD B_CTL_LOGO_C B_CTRL_LEFT B_CTRL_RIGHT CCD_PWR FBA_VREFC FBB_VREFC FBC_VREFC FBD_VREFC G_CTL_LOGO_C G_CTRL_LEFT G_CTRL_RIGHT LANVCC LCDVCC LED_B1 LED_B2 LED_G1 LED_G2 LED_PWR_TURBO LED_R1 LED_R2 MIC2-L MIC2-R MIC_VCC N56085203 N81221647 N81221898 N81223341 N81224802 N81224808 N82537287 N84112222 NVVDD R_CTL_LOGO_C R_CTRL_LEFT R_CTRL_RIGHT TYPEC1_USB0 TYPEC2_USB0 VDD1V8 WWAN_SIM1_PWR
net group W30-T1234B: nets LED_PWR_LOGO LINLVP LIP LVN RIP SPKLN_L SPKLP_L SPKRN_L SPKRP_L
net group W40-T1234B: nets N56849294

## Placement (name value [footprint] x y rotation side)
C1  4.7u/6.3V_4  [C0402]  267.04 214.52 90 top
C2  0.1u/6.3V_2  [C0201]  265.48 214.52 270 top
C3  0.1u/6.3V_2  [C0201]  266.2 214.52 270 top
C4  0.1u/6.3V_2  [C0201]  276.18 214.09 270 top
C5  0.1u/6.3V_2  [C0201]  276.9 214.09 270 top
C6  0.47u/25V_2  [C0201]  277.39 213.19 0 top
C7  0.1u/6.3V_2  [C0201]  274.79 211.5 90 top
C8  *68p/25V_2  [C0201]  275.5 211.5 90 top
C9  0.1u/6.3V_2  [C0201]  276.22 211.5 90 top
C10  *3.3p/25V_2  [C0201]  276.93 211.5 90 top
C11  0.01u/50V_4  [C0402]  265.43 209.14 270 top
C12  *47u/6.3V_8  [C0805]  268.89 208.32 90 top
C13  *2.2u/10V_4  [C0402]  266.12 206.19 180 top
C14  *6.8p/50V_2  [C0201]  267.59 205.23 270 top
C15  *68p/25V_2  [C0201]  268.3 205.23 270 top
C16  100p/50V_2  [C0201]  266.81 205.22 270 top
C17  0.1u/6.3V_2  [C0201]  268.46 204.34 0 top
C18  *2.2u/25V_4  [C0402]  209.22 203.81 90 top
C19  *3.3p/25V_2  [C0201]  208.35 203.77 90 top
C20  *68p/25V_2  [C0201]  207.59 203.76 90 top
C21  0.1u/6.3V_2  [C0201]  267.19 203.16 90 top
C22  10u/6.3V_4  [C0402]  268.27 203.11 270 top
C23  10u/6.3V_4  [C0402]  268.13 200.65 270 top
C24  *68p/25V_2  [C0201]  178.88 199.1 270 top
C25  *3.3p/25V_2  [C0201]  178.11 199.1 270 top
C26  *2.2u/25V_4  [C0402]  177.2 198.99 270 top
C27  10u/6.3V_4  [C0402]  268.13 198.87 90 top
C28  180p/25V_2  [C0201]  278.62 187.22 180 top
C29  *2.2u/25V_4  [C0402]  184.2 186.92 90 top
C30  *3.3p/25V_2  [C0201]  183.18 186.87 90 top
C31  *68p/25V_2  [C0201]  185.14 186.85 90 top
C32  220p/25V_2  [C0201]  278.62 186.08 180 top
C33  220p/25V_2  [C0201]  278.62 184.94 180 top
C34  0.1u/6.3V_2  [C0201]  268.48 184.37 90 top
C35  0.1u/6.3V_2  [C0201]  202.82 184.11 270 top
C36  1000p/25V_2  [C0201]  267.74 184.11 90 top
C37  *6.8p/50V_2  [C0201]  266.89 183.64 0 top
C38  *1000p/25V_2  [C0201]  204.35 183.35 0 top
C39  0.1u/6.3V_2  [C0201]  205.36 183.35 180 top
C40  *47p/25V_2  [C0201]  184.15 163.79 180 top
C41  10p/25V_2  [C0201]  163.15 161.2 180 top
C42  10p/25V_2  [C0201]  163.15 160.44 180 top
C43  10p/25V_2  [C0201]  163.15 159.68 180 top
C44  47u/6.3V_6  [C0603]  166.95 159.58 0 top
C45  0.1u/6.3V_2  [C0201]  157.36 158.77 90 top
C46  0.1u/6.3V_2  [C0201]  158.12 158.77 90 top
C47  0.1u/6.3V_2  [C0201]  154.54 158.75 90 top
C48  0.1u/6.3V_2  [C0201]  155.3 158.75 90 top
C49  0.1u/6.3V_2  [C0201]  153.27 157.61 90 top
C50  0.1u/6.3V_2  [C0201]  154.03 157.61 90 top
C51  0.1u/6.3V_2  [C0201]  155.94 157.61 90 top
C52  0.1u/6.3V_2  [C0201]  156.7 157.61 90 top
C53  0.1u/6.3V_2  [C0201]  158.61 157.61 90 top
C54  0.1u/6.3V_2  [C0201]  159.37 157.61 90 top
C55  0.1u/6.3V_2  [C0201]  161.8 157.57 90 top
C56  0.1u/6.3V_2  [C0201]  162.56 157.57 90 top
C57  0.1u/6.3V_2  [C0201]  160.05 156.48 90 top
C58  0.1u/6.3V_2  [C0201]  160.81 156.48 90 top
C59  10u/6.3V_4  [C0402]  167.31 156.15 180 top
C60  10u/6.3V_4  [C0402]  165.38 155.22 180 top
C61  10u/6.3V_4  [C0402]  163.39 155.21 180 top
C62  8.2p/50V_2  [C0201]  130.54 155.19 0 top
C63  8.2p/50V_2  [C0201]  132.45 154.91 0 top
C64  10u/6.3V_4  [C0402]  139.82 153.97 0 top
C65  10u/6.3V_4  [C0402]  135.04 153.4 180 top
C66  10u/6.3V_4  [C0402]  133.55 153.32 90 top
C67  10u/6.3V_4  [C0402]  130.42 153.26 270 top
C68  10u/6.3V_4  [C0402]  162.12 153.21 0 top
C69  10u/6.3V_4  [C0402]  141.44 152.31 0 top
C70  10u/6.3V_4  [C0402]  148.18 152.2 90 top
C71  8.2p/50V_2  [C0201]  132.04 151.31 180 top
C72  *10p/25V_2  [C0201]  165.15 151 0 top
C73  *10u/6.3V_4  [C0402]  138.93 151 0 top
C74  10u/6.3V_4  [C0402]  134.88 150.61 270 top
C75  10u/6.3V_4  [C0402]  154.64 150.32 0 top
C76  10u/6.3V_4  [C0402]  149.67 149.14 180 top
C77  10p/25V_2  [C0201]  158.07 149.13 180 top
C78  10u/6.3V_4  [C0402]  142.76 149.07 180 top
C79  10u/6.3V_4  [C0402]  147.07 149.06 180 top
C80  10u/6.3V_4  [C0402]  145.04 149.05 180 top
C81  10u/6.3V_4  [C0402]  140.33 149.04 180 top
C82  8.2p/50V_2  [C0201]  133.79 148.98 270 top
C83  10u/6.3V_4  [C0402]  137.84 148.97 180 top
C84  1u/10V_2  [C0201]  167.91 148.88 0 top
C85  *22u/6.3V_6  [C0603]  155.27 148.86 0 top
C86  *1u/10V_2  [C0201]  168.09 147.65 0 top
C87  *8.2p/50V_2  [C0201]  165.42 147.61 0 top
C88  10u/6.3V_4  [C0402]  135.25 147.54 180 top
C89  47u/6.3V_6  [C0603]  161.38 147.47 0 top
C90  47u/6.3V_6  [C0603]  158.75 147.44 180 top
C91  10u/6.3V_4  [C0402]  137.16 147.41 180 top
C92  8.2p/50V_2  [C0201]  129.79 147.32 270 top
C93  *1u/10V_2  [C0201]  168.11 146.68 0 top
C94  10u/6.3V_4  [C0402]  166.42 146.64 270 top
C95  220u/2V_7343H1.0  [CC7343]  152.61 145.78 180 top
C96  *220u/2V_7343H1.0  [CC7343]  115.01 182.79 90 top
C97  8.2p/50V_2  [C0201]  166.14 145.41 0 top
C98  47u/6.3V_6  [C0603]  162.64 145.29 270 top
C99  47u/6.3V_6  [C0603]  161.22 145.29 270 top
C100  47u/6.3V_6  [C0603]  159.8 145.28 270 top
C101  8.2p/50V_2  [C0201]  130.99 145.05 270 top
C102  8.2p/50V_2  [C0201]  132.41 144.44 270 top
C103  10p/25V_2  [C0201]  133.76 144.41 270 top
C104  10u/6.3V_4  [C0402]  136.94 143.95 270 top
C105  10p/25V_2  [C0201]  165.68 143.1 0 top
C106  10u/6.3V_4  [C0402]  135 142.97 90 top
C107  *10u/6.3V_4  [C0402]  135.97 142.97 270 top
C108  1u/10V_2  [C0201]  167.43 142.81 90 top
C109  47u/6.3V_6  [C0603]  161.33 142.63 270 top
C110  47u/6.3V_6  [C0603]  159.91 142.63 270 top
C111  47u/6.3V_6  [C0603]  162.75 142.63 270 top
C112  47u/6.3V_6  [C0603]  158.48 142.62 270 top
C113  10u/6.3V_4  [C0402]  164.21 142.58 90 top
C114  10u/6.3V_4  [C0402]  137.42 141.91 90 top
C115  10p/25V_2  [C0201]  134.57 141.16 180 top
C116  *220u/2V_7343H1.0  [CC7343]  152.63 141.05 180 top
C117  *220u/2V_7343H1.0  [CC7343]  162.31 182.84 90 top
C118  8.2p/50V_2  [C0201]  157.88 140.86 0 top
C119  *1u/10V_2  [C0201]  167.91 140.85 0 top
C120  *47u/6.3V_6  [C0603]  161.29 139.7 90 top
C121  *47u/6.3V_6  [C0603]  162.71 139.7 90 top
C122  8.2p/50V_2  [C0201]  134.27 139.54 270 top
C123  10u/6.3V_4  [C0402]  137.62 138.22 270 top
C124  10u/6.3V_4  [C0402]  159.71 138.18 0 top
C125  2.2p/25V_2  [C0201]  156.96 137.94 90 top
C126  22u/6.3V_6  [C0603]  158.13 137.73 90 top
C127  22u/6.3V_6  [C0603]  153.69 137.38 180 top
C128  47u/6.3V_6  [C0603]  143.28 137.29 180 top
C129  10u/6.3V_4  [C0402]  139.02 137.28 90 top
C130  47u/6.3V_6  [C0603]  146.1 137.24 0 top
C131  10u/6.3V_4  [C0402]  140.83 137.17 180 top
C132  10u/6.3V_4  [C0402]  159.71 137 0 top
C133  10u/6.3V_4  [C0402]  162.88 136.88 180 top
C134  1u/10V_2  [C0201]  165.99 136.26 0 top
C135  10u/6.3V_4  [C0402]  136.95 135.91 180 top
C136  5G@68p/50V_2  [C0201]  150.7 135.9 90 top
C137  10p/25V_2  [C0201]  164.77 135.9 270 top
C138  2.2p/25V_2  [C0201]  143.05 135.67 180 top
C139  10p/25V_2  [C0201]  162.97 135.47 0 top
C140  *6.8p/50V_2  [C0201]  224.01 133.59 90 top
C141  6.8p/50V_2  [C0201]  243.93 134.04 270 top
C142  6.8p/50V_2  [C0201]  231.94 133.75 270 top
C143  5G@68p/50V_2  [C0201]  114.59 121.24 180 top
C144  *6.8p/50V_2  [C0201]  252.77 120.96 270 top
C145  *3.3p/25V_2  [C0201]  114.6 120.4 180 top
C146  *68p/25V_2  [C0201]  114.58 119.66 180 top
C147  6.8p/50V_2  [C0201]  237.46 118.62 180 top
C148  *2.2u/10V_4  [C0402]  232.13 111.34 90 top
C149  *68p/25V_2  [C0201]  233.83 111.27 90 top
C150  *6.8p/50V_2  [C0201]  233.08 111.25 90 top
C151  1u/10V_2  [C0201]  189.41 105.75 0 top
C152  *1u/10V_2  [C0201]  189.41 105.04 0 top
C153  10u/6.3V_4  [C0402]  189.26 103.97 180 top
C154  1u/10V_2  [C0201]  182.5 103.44 180 top
C155  1u/10V_2  [C0201]  128.43 103.24 270 top
C156  1u/10V_2  [C0201]  138.84 102.96 90 top
C157  *10u/6.3V_4  [C0402]  189.41 102.77 180 top
C158  1u/10V_2  [C0201]  173.43 102.76 270 top
C159  10u/6.3V_4  [C0402]  164.6 102.73 90 top
C160  *1u/10V_2  [C0201]  153.41 102.43 270 top
C161  0.1u/6.3V_2  [C0201]  186.54 102.35 270 top
C162  2.2u/10V_4  [C0402]  187.89 102.22 90 top
C163  2.2p/25V_2  [C0201]  146.94 102.12 90 top
C164  1u/10V_2  [C0201]  154.61 102.05 270 top
C165  *1u/10V_2  [C0201]  158.52 101.84 270 top
C166  1u/10V_2  [C0201]  149.89 101.74 90 top
C167  10u/6.3V_4  [C0402]  156.7 101.69 90 top
C168  10u/6.3V_4  [C0402]  160.02 101.69 90 top
C169  10u/6.3V_4  [C0402]  151.73 101.34 270 top
C170  12p/25V_2  [C0201]  153.24 100.65 90 top
C171  *1u/10V_2  [C0201]  164.04 100.24 270 top
C172  *1u/10V_2  [C0201]  157.03 99.66 90 top
C173  1000p/25V_2  [C0201]  301.99 99.65 0 top
C174  10u/6.3V_4  [C0402]  169.78 99.58 180 top
C175  1u/10V_2  [C0201]  316.66 99.41 90 top
C176  *10u/6.3V_4  [C0402]  162.57 99.39 90 top
C177  1u/10V_2  [C0201]  123.75 99.33 90 top
C178  0.1u/6.3V_2  [C0201]  314.56 98.98 90 top
C179  12p/25V_2  [C0201]  158.52 98.95 90 top
C180  10u/6.3V_4  [C0402]  313.72 98.95 270 top
C181  47u/6.3V_6  [C0603]  50.68 98.64 0 top
C182  *1u/10V_2  [C0201]  153.24 98.51 270 top
C183  *0.1u/6.3V_2  [C0201]  147.04 98.16 90 top
C184  1u/10V_2  [C0201]  177.6 98.01 90 top
C185  2.2u/10V_4  [C0402]  42.8 97.88 180 top
C186  *10u/6.3V_4  [C0402]  189.56 97.73 180 top
C187  1u/10V_2  [C0201]  308.68 97.32 270 top
C188  2.2u/10V_4  [C0402]  47.4 97.17 90 top
C189  *0.1u/6.3V_2  [C0201]  16.61 97.12 0 top
C190  1u/10V_2  [C0201]  187.28 96.91 180 top
C191  10p/25V_2  [C0201]  35.44 96.74 0 top
C192  10p/25V_2  [C0201]  36.71 96.74 180 top
C193  22u/6.3V_6  [C0603]  60.58 96.69 180 top
C194  47u/6.3V_6  [C0603]  42.8 96.61 180 top
C195  47u/6.3V_6  [C0603]  45.6 96.61 0 top
C196  10u/6.3V_4  [C0402]  133.68 96.56 0 top
C197  10u/6.3V_4  [C0402]  189.11 96.48 180 top
C198  10u/6.3V_4  [C0402]  148.46 96.47 0 top
C199  *1u/10V_2  [C0201]  187.28 96.15 180 top
C200  *0.1u/6.3V_2  [C0201]  163.55 95.97 0 top
C201  2.2u/10V_4  [C0402]  53.85 95.72 270 top
C202  2.2u/10V_4  [C0402]  54.87 95.72 270 top
C203  *1u/10V_2  [C0201]  187.28 95.39 180 top
C204  2.2u/10V_4  [C0402]  42.17 95.34 180 top
C205  22u/6.3V_6  [C0603]  60.61 95.27 180 top
C206  0.47u/25V_2  [C0201]  10.29 95.24 270 top
C207  0.47u/25V_2  [C0201]  11.05 95.24 270 top
C208  *2.2u/10V_4  [C0402]  163.55 95.01 180 top
C209  1u/10V_2  [C0201]  187.15 94.4 270 top
C210  1u/10V_2  [C0201]  187.86 94.4 270 top
C211  *1u/10V_2  [C0201]  188.57 94.4 270 top
C212  *1u/10V_2  [C0201]  189.28 94.4 270 top
C213  5G@47u/6.3V_8  [C0805]  303.49 93.88 270 top
C214  22u/6.3V_6  [C0603]  60.61 93.84 180 top
C215  2.2u/10V_4  [C0402]  48.26 93.82 180 top
C216  18p/25V_2  [C0201]  46.99 93.69 90 top
C217  5G@1u/10V_2  [C0201]  304.84 93.68 90 top
C218  220u/6.3V_3528H1.9  [C3528]  300.76 93.29 270 top
C219  0.33u/25V_2  [C0201]  30.23 93.56 180 top
C220  *0.1u/6.3V_2  [C0201]  18.93 93.28 270 top
C221  *0.1u/6.3V_2  [C0201]  19.69 93.28 270 top
C222  *1u/10V_2  [C0201]  20.45 93.28 270 top
C223  10u/6.3V_4  [C0402]  101.39 93.07 270 top
C224  0.1u/6.3V_2  [C0201]  48.01 92.93 180 top
C225  5G@8.2p/50V_2  [C0201]  307.68 92.81 0 top
C226  0.1u/6.3V_2  [C0201]  60.37 92.78 0 top
C227  0.33u/25V_2  [C0201]  30.23 92.67 180 top
C228  0.22u/25V_2  [C0201]  44.71 92.67 180 top
C229  5G@10p/25V_2  [C0201]  307.66 92.07 0 top
C230  220p/25V_2  [C0201]  60.38 92.05 180 top
C231  10u/6.3V_4  [C0402]  63.38 92.04 270 top
C232  10u/6.3V_4  [C0402]  64.39 92.04 270 top
C233  0.22u/25V_2  [C0201]  44.71 91.91 180 top
C234  220u/6.3V_3528H1.9  [C3528]  296.44 90.97 0 top
C235  0.22u/25V_2  [C0201]  30.23 91.53 180 top
C236  *6.8p/50V_2  [C0201]  12.03 91.52 90 top
C237  220p/25V_2  [C0201]  62.11 91.4 180 top
C238  5G@6.8p/50V_2  [C0201]  307.65 91.33 0 top
C239  0.22u/25V_2  [C0201]  44.71 91.02 180 top
C240  *47u/6.3V_8  [C0805]  99.61 90.95 180 top
C241  0.47u/25V_2  [C0201]  10.54 90.92 90 top
C242  0.47u/25V_2  [C0201]  11.31 90.92 90 top
C243  0.22u/25V_2  [C0201]  30.23 90.64 180 top
C244  5G@39p/25V_2  [C0201]  300.1 89.75 270 top
C245  10u/6.3V_4  [C0402]  65.03 90.51 180 top
C246  0.22u/25V_2  [C0201]  44.71 90.26 180 top
C247  1u/10V_2  [C0201]  188.98 90.26 0 top
C248  5G@3.3p/25V_2  [C0201]  298.2 88.74 270 top
C249  5G@33p/25V_2  [C0201]  297.44 88.74 270 top
C250  5G@18p/25V_2  [C0201]  296.68 88.74 270 top
C251  0.1u/6.3V_2  [C0201]  187.3 89.75 0 top
C252  0.22u/25V_2  [C0201]  30.23 89.5 180 top
C253  *1u/10V_2  [C0201]  188.98 89.5 0 top
C254  0.22u/25V_2  [C0201]  44.71 89.37 180 top
C255  *0.1u/6.3V_2  [C0201]  71.63 89.12 180 top
C256  0.022u/25V_4  [C0402]  169.37 89.12 0 top
C257  2.2u/10V_4  [C0402]  187.38 88.89 180 top
C258  *1u/10V_2  [C0201]  155.68 88.66 0 top
C259  0.22u/25V_2  [C0201]  30.23 88.61 180 top
C260  0.22u/25V_2  [C0201]  44.71 88.61 180 top
C261  *10u/6.3V_4  [C0402]  189.11 88.61 180 top
C262  1u/10V_2  [C0201]  140.24 87.92 270 top
C263  5G@0.1u/25V_2  [C0201]  310.65 88.03 0 top
C264  0.22u/25V_2  [C0201]  44.71 87.72 180 top
C265  *1u/10V_2  [C0201]  150.83 87.67 270 top
C266  12p/25V_2  [C0201]  148.06 87.62 270 top
C267  *0.1u/6.3V_2  [C0201]  75.19 87.59 0 top
C268  10u/6.3V_4  [C0402]  173.64 87.52 90 top
C269  *1u/10V_2  [C0201]  165.33 87.47 90 top
C270  0.33u/25V_2  [C0201]  30.23 87.34 180 top
C271  10u/6.3V_4  [C0402]  189.23 87.34 180 top
C272  1u/10V_2  [C0201]  182.88 87.31 270 top
C273  1u/10V_2  [C0201]  153.09 87.29 270 top
C274  0.22u/25V_2  [C0201]  44.71 86.96 180 top
C275  1u/10V_2  [C0201]  130.58 86.88 270 top
C276  1u/10V_2  [C0201]  151.72 86.86 270 top
C277  12p/25V_2  [C0201]  164.01 86.73 270 top
C278  *1u/10V_2  [C0201]  159.72 86.7 270 top
C279  *1u/10V_2  [C0201]  162.51 86.7 270 top
C280  10u/6.3V_4  [C0402]  157.1 86.5 90 top
C281  0.33u/25V_2  [C0201]  30.23 86.45 180 top
C282  10u/6.3V_4  [C0402]  154.64 86.04 270 top
C283  10u/6.3V_4  [C0402]  166.47 85.79 180 top
C284  10u/6.3V_4  [C0402]  123.57 85.54 270 top
C285  0.1u/25V_2  [C0201]  290.07 85.31 270 top
C286  2.2p/25V_2  [C0201]  153.47 85.26 90 top
C287  0.1u/6.3V_2  [C0201]  60.33 85.18 0 top
C288  5G@0.22u/6.3V_2  [C0201]  304.93 85.13 0 top
C289  *220p/25V_2  [C0201]  288.42 84.93 180 top
C290  10u/6.3V_4  [C0402]  134.57 84.85 270 top
C291  10u/6.3V_4  [C0402]  158.3 84.67 90 top
C292  10u/6.3V_4  [C0402]  151.79 84.54 270 top
C293  220p/25V_2  [C0201]  62.03 84.42 0 top
C294  220p/25V_2  [C0201]  63.02 84.42 180 top
C295  *0.1u/6.3V_2  [C0201]  148.14 84.39 90 top
C296  5G@0.22u/6.3V_2  [C0201]  304.93 84.37 0 top
C297  10u/6.3V_4  [C0402]  145.47 84.34 180 top
C298  2.2p/25V_2  [C0201]  157.18 84.24 90 top
C299  1u/10V_2  [C0201]  159.87 84.19 90 top
C300  1u/10V_2  [C0201]  161.75 84.19 90 top
C301  22u/6.3V_6  [C0603]  60.2 84.04 180 top
C302  12p/25V_2  [C0201]  153.57 84.01 270 top
C303  5G@1u/10V_2  [C0201]  300.1 83.84 180 top
C304  *10u/6.3V_4  [C0402]  149.84 83.68 90 top
C305  *1u/10V_2  [C0201]  167.2 83.49 90 top
C306  10u/6.3V_4  [C0402]  178.9 83.48 270 top
C307  1u/10V_2  [C0201]  164.29 83.05 270 top
C308  5G@100p/50V_2  [C0201]  301.76 83.02 180 top
C309  *10u/6.3V_4  [C0402]  189.23 82.89 180 top
C310  15p/25V_2  [C0201]  211 82.89 180 top
C311  22u/6.3V_6  [C0603]  60.2 82.51 180 top
C312  18p/25V_2  [C0201]  209.81 82 0 top
C313  10u/6.3V_4  [C0402]  189.11 81.62 180 top
C314  1u/10V_2  [C0201]  187.43 81.57 270 top
C315  0.022u/25V_4  [C0402]  159.79 81.5 90 top
C316  *2.2u/10V_4  [C0402]  164.6 81.5 90 top
C317  *0.1u/6.3V_2  [C0201]  165.61 81.5 270 top
C318  0.47u/25V_2  [C0201]  10.29 81.27 270 top
C319  0.47u/25V_2  [C0201]  11.05 81.27 270 top
C320  22u/6.3V_6  [C0603]  60.2 80.99 180 top
C321  *220p/25V_2  [C0201]  292.36 80.73 90 top
C322  *0.1u/6.3V_2  [C0201]  16.96 80.64 270 top
C323  *47u/6.3V_8  [C0805]  102.75 80.61 0 top
C324  2.2u/10V_4  [C0402]  38.45 80.48 180 top
C325  *6.8p/50V_2  [C0201]  11.2 80.42 0 top
C326  10u/6.3V_4  [C0402]  311.86 80.28 90 top
C327  0.1u/6.3V_2  [C0201]  312.76 80.25 270 top
C328  0.1u/6.3V_2  [C0201]  313.59 80.23 270 top
C329  *3.3p/25V_2  [C0201]  159.12 80.12 270 top
C330  *68p/25V_2  [C0201]  158.34 80.11 270 top
C331  *2.2u/10V_4  [C0402]  157.44 80.08 270 top
C332  5G@47u/6.3V_8  [C0805]  305.57 79.84 180 top
C333  0.1u/6.3V_2  [C0201]  275.17 79.7 180 top
C334  2.2u/10V_4  [C0402]  42.88 79.48 90 top
C335  10p/25V_2  [C0201]  30.86 79.46 0 top
C336  10p/25V_2  [C0201]  32.13 79.46 180 top
C337  47u/6.3V_6  [C0603]  44.81 79.46 90 top
C338  47u/6.3V_6  [C0603]  41.06 79.27 0 top
C339  47u/6.3V_6  [C0603]  38.41 79.27 180 top
C340  *0.1u/6.3V_2  [C0201]  275.17 78.93 180 top
C341  10u/6.3V_4  [C0402]  315.52 78.89 0 top
C342  *47u/6.3V_8  [C0805]  102.75 78.58 0 top
C343  0.1u/6.3V_2  [C0201]  270.7 78.55 180 top
C344  2.2u/10V_4  [C0402]  37.6 78.07 180 top
C345  0.1u/6.3V_2  [C0201]  63.12 77.94 90 top
C346  *5G@47u/6.3V_8  [C0805]  305.57 77.86 180 top
C347  0.1u/6.3V_2  [C0201]  270.69 77.83 180 top
C348  2.2u/10V_4  [C0402]  46.61 77.81 270 top
C349  2.2u/10V_4  [C0402]  47.63 77.81 270 top
C350  180p/25V_2  [C0201]  172.19 77.64 270 top
C351  10u/6.3V_4  [C0402]  312.03 77.37 90 top
C352  0.1u/6.3V_2  [C0201]  270.69 77.11 180 top
C353  0.1u/6.3V_2  [C0201]  312.88 77.03 270 top
C354  0.47u/25V_2  [C0201]  10.54 76.84 90 top
C355  0.47u/25V_2  [C0201]  11.43 76.84 90 top
C356  *0.1u/6.3V_2  [C0201]  17.28 76.59 270 top
C357  *1u/10V_2  [C0201]  18.04 76.59 270 top
C358  *0.1u/6.3V_2  [C0201]  18.8 76.59 270 top
C359  18p/25V_2  [C0201]  42.42 76.39 90 top
C360  0.33u/25V_2  [C0201]  25.66 76.29 180 top
C361  10u/6.3V_4  [C0402]  270.74 76.24 0 top
C362  0.1u/6.3V_2  [C0201]  309.14 76.18 0 top
C363  0.1u/6.3V_2  [C0201]  100.33 75.91 90 top
C364  0.1u/6.3V_2  [C0201]  101.1 75.91 90 top
C365  0.1u/6.3V_2  [C0201]  101.86 75.91 90 top
C366  0.1u/6.3V_2  [C0201]  102.62 75.91 90 top
C367  5G@0.1u/6.3V_2  [C0201]  304.37 75.86 180 top
C368  0.1u/6.3V_2  [C0201]  98.15 75.53 0 top
C369  180p/25V_2  [C0201]  168.02 75.53 90 top
C370  0.33u/25V_2  [C0201]  25.66 75.4 180 top
C371  0.22u/25V_2  [C0201]  40.14 75.4 180 top
C372  10u/6.3V_4  [C0402]  309.05 75.3 180 top
C373  0.1u/6.3V_2  [C0201]  169.9 75.27 270 top
C374  0.1u/6.3V_2  [C0201]  171.71 75.27 90 top
C375  0.1u/6.3V_2  [C0201]  175.16 75.27 90 top
C376  0.1u/6.3V_2  [C0201]  178.72 75.27 90 top
C377  180p/25V_2  [C0201]  182.63 75.27 270 top
C378  5G@1u/10V_2  [C0201]  304.37 75.1 180 top
C379  TPM@0.1u/6.3V_2  [C0201]  237.48 74.92 180 top
C380  SUB@10u/6.3V_4  [C0402]  300.31 74.92 180 top
C381  0.1u/6.3V_2  [C0201]  98.14 74.77 0 top
C382  0.22u/25V_2  [C0201]  40.14 74.64 180 top
C383  0.22u/25V_2  [C0201]  25.66 74.26 180 top
C384  SUB@0.1u/6.3V_2  [C0201]  300.17 73.96 180 top
C385  TPM@0.1u/6.3V_2  [C0201]  237.48 73.91 180 top
C386  10u/6.3V_4  [C0402]  98.14 73.82 180 top
C387  0.22u/25V_2  [C0201]  40.14 73.75 180 top
C388  0.22u/25V_2  [C0201]  25.66 73.37 180 top
C389  SUB@10u/6.3V_4  [C0402]  300.32 73 180 top
C390  0.22u/25V_2  [C0201]  40.14 72.99 180 top
C391  1u/10V_2  [C0201]  268.46 72.89 180 top
C392  0.01u/10V_2  [C0201]  277.25 72.65 0 top
C393  10u/6.3V_4  [C0402]  98.05 72.61 180 top
C394  0.1u/6.3V_2  [C0201]  155.81 72.57 0 top
C395  180p/25V_2  [C0201]  164.64 72.44 180 top
C396  0.22u/25V_2  [C0201]  25.66 72.23 180 top
C397  10u/6.3V_4  [C0402]  314.17 72.16 0 top
C398  0.22u/25V_2  [C0201]  40.14 72.1 180 top
C399  SUB@0.1u/6.3V_2  [C0201]  300.53 72.04 180 top
C400  *1u/10V_2  [C0201]  306.52 72.03 0 top
C401  10u/6.3V_4  [C0402]  277.37 71.63 0 top
C402  **0.1u/6.3V_2  [C0201]  228.1 71.58 0 top
C403  0.22u/25V_2  [C0201]  25.66 71.34 180 top
C404  0.22u/25V_2  [C0201]  40.14 71.34 180 top
C405  0.1u/6.3V_2  [C0201]  313.55 71.08 180 top
C406  100p/50V_2  [C0201]  320.83 70.98 0 top
C407  2.2u/10V_4  [C0402]  314.94 70.93 0 top
C408  *SUB@10p/25V_2  [C0201]  292.36 69.56 0 top
C409  1u/10V_2  [C0201]  215.82 70.82 180 top
C410  0.22u/25V_2  [C0201]  40.14 70.45 180 top
C411  *47u/6.3V_8  [C0805]  98.12 70.34 90 top
C412  *47u/6.3V_8  [C0805]  100.28 70.34 90 top
C413  SUB@2.2u/10V_4  [C0402]  298 70.22 90 top
C414  0.33u/25V_2  [C0201]  25.66 70.07 180 top
C415  0.22u/25V_2  [C0201]  15.55 69.94 0 top
C416  0.22u/25V_2  [C0201]  40.14 69.69 180 top
C417  SUB@330p/25V_2  [C0201]  294.77 69.61 270 top
C418  SUB@330p/25V_2  [C0201]  295.49 69.61 270 top
C419  SUB@330p/25V_2  [C0201]  296.25 69.61 270 top
C420  SUB@330p/25V_2  [C0201]  293.78 69.6 270 top
C421  1u/10V_2  [C0201]  318.34 69.56 90 top
C422  1u/10V_2  [C0201]  319.76 69.56 90 top
C423  0.1u/6.3V_2  [C0201]  320.5 69.56 270 top
C424  1u/10V_2  [C0201]  215.58 69.46 270 top
C425  0.1u/6.3V_2  [C0201]  186.06 69.43 270 top
C426  0.1u/6.3V_2  [C0201]  186.82 69.43 270 top
C427  10u/6.3V_4  [C0402]  214.36 69.43 0 top
C428  0.22u/25V_2  [C0201]  22.79 69.13 180 top
C429  0.22u/25V_2  [C0201]  15.55 69.18 0 top
C430  0.33u/25V_2  [C0201]  25.66 69.18 180 top
C431  **0.1u/6.3V_2  [C0201]  227.84 68.95 180 top
C432  *68p/25V_2  [C0201]  271.84 68.7 270 top
C433  *6.8p/50V_2  [C0201]  272.58 68.68 270 top
C434  0.1u/6.3V_2  [C0201]  165.31 68.63 180 top
C435  0.22u/25V_2  [C0201]  22.79 68.26 180 top
C436  1u/10V_2  [C0201]  210.28 68.45 270 top
C437  *10p/25V_2  [C0201]  161.8 68.42 0 top
C438  1u/10V_2  [C0201]  215.58 68.41 90 top
C439  10u/6.3V_4  [C0402]  305.81 67.94 270 top
C440  0.1u/6.3V_2  [C0201]  165.31 67.81 180 top
C441  0.1u/6.3V_2  [C0201]  306.77 67.77 90 top
C442  4.7u/6.3V_4  [C0402]  16.31 67.71 270 top
C443  0.1u/6.3V_2  [C0201]  20.03 67.55 0 top
C444  *0.1u/6.3V_2  [C0201]  227.31 67.06 90 top
C445  10u/6.3V_4  [C0402]  318.52 67.02 0 top
C446  180p/25V_2  [C0201]  186.92 66.42 0 top
C447  33p/25V_2  [C0201]  306.3 66.33 180 top
C448  1u/10V_2  [C0201]  165.08 66.26 180 top
C449  *0.1u/6.3V_2  [C0201]  227.23 65.67 0 top
C450  33p/25V_2  [C0201]  306.3 65.62 180 top
C451  0.1u/6.3V_2  [C0201]  219.25 65.58 90 top
C452  *180p/25V_2  [C0201]  186.93 65.45 0 top
C453  10u/6.3V_4  [C0402]  212.15 65.02 270 top
C454  0.1u/6.3V_2  [C0201]  22.63 64.94 0 top
C455  SUB@2.2u/10V_4  [C0402]  306.13 64.75 0 top
C456  0.1u/6.3V_2  [C0201]  163.99 64.5 270 top
C457  TPM@0.1u/6.3V_2  [C0201]  240.65 64.16 270 top
C458  TPM@0.1u/6.3V_2  [C0201]  241.67 64.16 270 top
C459  TPM@10u/6.3V_4  [C0402]  242.79 64.05 90 top
C460  2.2u/10V_4  [C0402]  14.63 63.92 0 top
C461  47u/6.3V_6  [C0603]  208.88 63.7 180 top
C462  *SUB@1000p/25V_2  [C0201]  306.71 63.48 180 top
C463  SUB@0.1u/6.3V_2  [C0201]  297.16 62.96 180 top
C464  0.1u/6.3V_2  [C0201]  186.06 62.95 90 top
C465  1000p/25V_2  [C0201]  186.93 62.95 270 top
C466  0.1u/6.3V_2  [C0201]  217.2 62.89 270 top
C467  *SUB@1000p/25V_2  [C0201]  306.03 62.51 180 top
C468  0.01u/10V_2  [C0201]  14.83 62.28 180 top
C469  1u/10V_6  [C0603]  317.88 62.22 180 top
C470  *180p/25V_2  [C0201]  164.72 62.19 90 top
C471  1u/10V_6  [C0603]  315.85 61.81 90 top
C472  0.1u/6.3V_2  [C0201]  186.05 61.45 90 top
C473  0.1u/6.3V_2  [C0201]  218.97 61.41 180 top
C474  0.1u/6.3V_2  [C0201]  39.19 61.41 270 top
C475  0.1u/6.3V_2  [C0201]  39.96 61.41 270 top
C476  0.1u/6.3V_2  [C0201]  40.72 61.41 270 top
C477  0.1u/6.3V_2  [C0201]  41.48 61.41 270 top
C478  0.1u/6.3V_2  [C0201]  42.24 61.41 270 top
C479  0.1u/6.3V_2  [C0201]  43 61.41 270 top
C480  0.1u/6.3V_2  [C0201]  43.77 61.41 270 top
C481  0.1u/6.3V_2  [C0201]  44.53 61.41 270 top
C482  10u/6.3V_4  [C0402]  213.95 61.41 0 top
C483  0.1u/6.3V_2  [C0201]  313.24 61.35 0 top
C484  22p/25V_2  [C0201]  308.62 61.28 270 top
C485  10u/6.3V_4  [C0402]  311.4 61.16 0 top
C486  SUB@0.1u/6.3V_2  [C0201]  300.09 61.13 0 top
C487  47u/6.3V_6  [C0603]  211.77 61.11 0 top
C488  SUB@0.1u/6.3V_2  [C0201]  301.09 60.95 180 top
C489  SUB@1u/10V_2  [C0201]  302.08 60.95 180 top
C490  10u/6.3V_4  [C0402]  314.1 60.39 180 top
C491  0.1u/6.3V_2  [C0201]  165.01 60.25 270 top
C492  0.1u/6.3V_2  [C0201]  165.74 60.25 270 top
C493  10u/6.3V_4  [C0402]  215.18 60.23 0 top
C494  SUB@10u/6.3V_4  [C0402]  299.68 60.18 180 top
C495  0.22u/25V_2  [C0201]  20.35 59.98 270 top
C496  0.22u/25V_2  [C0201]  21.11 59.98 270 top
C497  0.01u/10V_2  [C0201]  21.87 59.98 270 top
C498  0.1u/6.3V_2  [C0201]  274.2 59.92 90 top
C499  0.01u/10V_2  [C0201]  273.43 59.91 270 top
C500  10u/6.3V_4  [C0402]  272.42 59.79 270 top
C501  SUB@2.2u/10V_4  [C0402]  301.4 59.72 180 top
C502  47u/6.3V_6  [C0603]  210.27 59.64 0 top
C503  10u/6.3V_4  [C0402]  215.17 58.97 0 top
C504  100p/50V_2  [C0201]  186.67 58.84 180 top
C505  47u/6.3V_6  [C0603]  210.27 58.03 0 top
C506  *3.3p/25V_2  [C0201]  212.09 57.89 180 top
C507  180p/25V_2  [C0201]  186.67 57.87 0 top
C508  *3.3p/25V_2  [C0201]  213.1 57.86 0 top
C509  10u/6.3V_4  [C0402]  215.17 57.79 0 top
C510  *6.8p/50V_2  [C0201]  20.9 57.13 90 top
C511  47u/6.3V_6  [C0603]  215.13 56.43 180 top
C512  47u/6.3V_6  [C0603]  211.26 56.41 0 top
C513  *0.1u/6.3V_2  [C0201]  254.26 56.05 90 top
C514  *2.2u/10V_4  [C0402]  213.21 55.83 270 top
